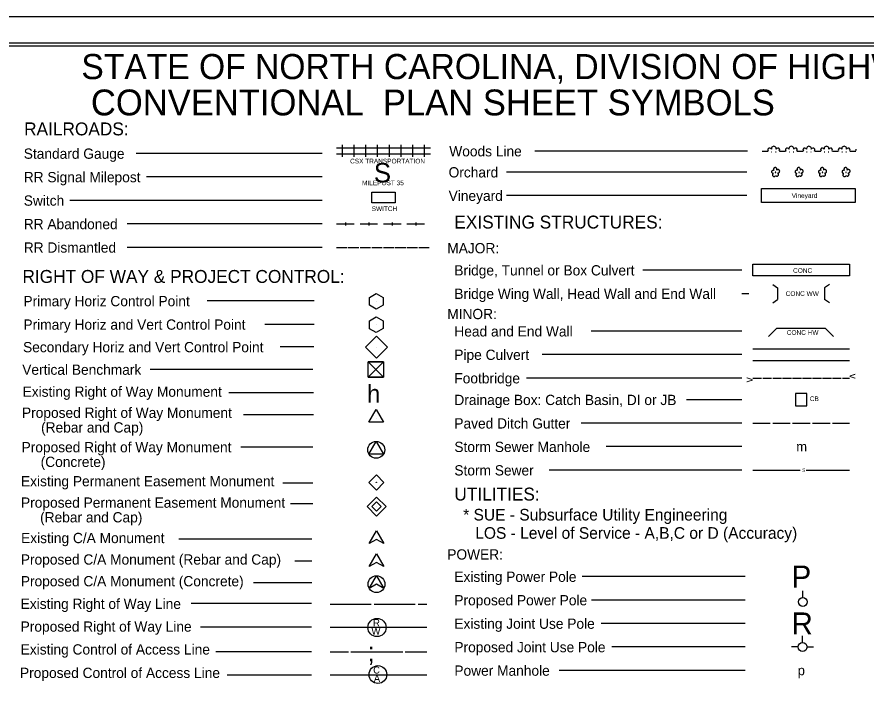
# Model space of a CAD drawing. Extents: x -2196851 to -2112651, y -24168 to 30832.
# Drawn here: x -2168716 to -2132538, y 2370 to 30832 of the extents above; entities that cross this region are included whole.
import ezdxf

# ---------------------------------------------------------------- set-up
doc = ezdxf.new("R2010")
doc.units = 0
for name, color, linetype in [('Default', 7, 'Continuous'), ('Prop ROW Permanent Easement CELL', 7, 'Continuous'), ('Sheet Plot Border Inside CELL', 7, 'Continuous'), ('Sheet Plot Border Outside CELL', 7, 'Continuous'), ('Sheet Symbology CELL', 7, 'Continuous')]:
    doc.layers.add(name, color=color, linetype=linetype)

msp = doc.modelspace()

# ---------------------------------------------------------------- linework, layer by layer
at = {"layer": 'Default'}
for p, q in [((-2153407, 18717), (-2153407, 18717)), ((-2153408, 17719), (-2153408, 17719)), ((-2153401, 16765), (-2153401, 16765)), ((-2153426, 15815), (-2153426, 15815)), ((-2153403, 11004), (-2153403, 11004))]:
    msp.add_line(p, q, dxfattribs=at)
for points in [[(-2153407, 18385), (-2153697, 18549), (-2153697, 18882), (-2153407, 19050), (-2153117, 18885), (-2153117, 18549), (-2153407, 18385)], [(-2153102, 16139), (-2153751, 15490), (-2153426, 15815), (-2153102, 15490), (-2153751, 16139)], [(-2153426, 15815), (-2153102, 16139), (-2153751, 16139), (-2153426, 15815)], [(-2153426, 15815), (-2153751, 15490), (-2153102, 15490), (-2153426, 15815)]]:
    msp.add_lwpolyline(points, dxfattribs=at)
for points in [[(-2153699, 17888), (-2153406, 18051), (-2153113, 17890), (-2153117, 17554), (-2153410, 17384), (-2153699, 17547)], [(-2153871, 16767), (-2153398, 17240), (-2152925, 16766), (-2153398, 16293)], [(-2153751, 16139), (-2153102, 16139), (-2153102, 15490), (-2153751, 15490)], [(-2153727, 11004), (-2153403, 11329), (-2153078, 11004), (-2153403, 10679)]]:
    msp.add_lwpolyline(points, close=True, dxfattribs=at)
msp.add_circle((-2153403, 11004), 6.32, dxfattribs=at)
at = {"layer": 'Prop ROW Permanent Easement CELL'}
msp.add_line((-2153394, 9974), (-2153394, 9974), dxfattribs=at)
for points in [[(-2153394, 10376), (-2152991, 9974), (-2153394, 9571), (-2153796, 9974)], [(-2153394, 10175), (-2153192, 9974), (-2153394, 9772), (-2153595, 9974)]]:
    msp.add_lwpolyline(points, close=True, dxfattribs=at)
at = {"layer": 'Sheet Plot Border Inside CELL'}
msp.add_lwpolyline([(-2196201, -23045), (-2112876, -23045), (-2112876, 29710), (-2196201, 29710)], close=True, dxfattribs=at)
at = {"layer": 'Sheet Plot Border Outside CELL'}
msp.add_lwpolyline([(-2196851, -24168), (-2112651, -24168), (-2112651, 30832), (-2196851, 30832)], close=True, dxfattribs=at)
at = {"layer": 'Sheet Symbology CELL'}
for p, q in [((-2154849, 24880), (-2154849, 25380)), ((-2154349, 24880), (-2154349, 25380)), ((-2153849, 24880), (-2153849, 25380)), ((-2153349, 24880), (-2153349, 25380)), ((-2152849, 24880), (-2152849, 25380)), ((-2152349, 24880), (-2152349, 25380)), ((-2151849, 24880), (-2151849, 25380)), ((-2151349, 24880), (-2151349, 25380)), ((-2155719, 25017), (-2163640, 25017)), ((-2155099, 25255), (-2154599, 25255)), ((-2155099, 25005), (-2154599, 25005)), ((-2154599, 25255), (-2154099, 25255)), ((-2154599, 25005), (-2154099, 25005)), ((-2154099, 25255), (-2153599, 25255)), ((-2154099, 25005), (-2153599, 25005)), ((-2153599, 25255), (-2153099, 25255)), ((-2153599, 25005), (-2153099, 25005)), ((-2153099, 25255), (-2152599, 25255)), ((-2153099, 25005), (-2152599, 25005)), ((-2152599, 25255), (-2152099, 25255)), ((-2152599, 25005), (-2152099, 25005)), ((-2152099, 25255), (-2151599, 25255)), ((-2152099, 25005), (-2151599, 25005)), ((-2151599, 25255), (-2151099, 25255)), ((-2151599, 25005), (-2151099, 25005)), ((-2137587, 25119), (-2146644, 25119)), ((-2136968, 25119), (-2136718, 25119)), ((-2136570, 25094), (-2136545, 25094)), ((-2136395, 25094), (-2136370, 25094)), ((-2136218, 25119), (-2135968, 25119)), ((-2135820, 25094), (-2135795, 25094)), ((-2135645, 25094), (-2135620, 25094)), ((-2135468, 25119), (-2135218, 25119)), ((-2135070, 25094), (-2135045, 25094)), ((-2134895, 25094), (-2134870, 25094)), ((-2134718, 25119), (-2134468, 25119)), ((-2134320, 25094), (-2134295, 25094)), ((-2134145, 25094), (-2134120, 25094)), ((-2133968, 25119), (-2133718, 25119)), ((-2133570, 25094), (-2133545, 25094)), ((-2133395, 25094), (-2133370, 25094)), ((-2133218, 25119), (-2132968, 25119)), ((-2155719, 24017), (-2163197, 24017)), ((-2137616, 24223), (-2147863, 24223)), ((-2137616, 23223), (-2147863, 23223)), ((-2155719, 23017), (-2166465, 23017)), ((-2154724, 22079), (-2154724, 21954)), ((-2153724, 22079), (-2153724, 21954)), ((-2152724, 22079), (-2152724, 21954)), ((-2151724, 22079), (-2151724, 21954)), ((-2155719, 22017), (-2164027, 22017)), ((-2155099, 22017), (-2154349, 22017)), ((-2154099, 22017), (-2153349, 22017)), ((-2153099, 22017), (-2152349, 22017)), ((-2152099, 22017), (-2151349, 22017)), ((-2155719, 21017), (-2164027, 21017)), ((-2155719, 21017), (-2164027, 21017)), ((-2155099, 21017), (-2154649, 21017)), ((-2154599, 21017), (-2154149, 21017)), ((-2154099, 21017), (-2153649, 21017)), ((-2153599, 21017), (-2153149, 21017)), ((-2153099, 21017), (-2152649, 21017)), ((-2152599, 21017), (-2152149, 21017)), ((-2152099, 21017), (-2151649, 21017)), ((-2151599, 21017), (-2151149, 21017)), ((-2137831, 20047), (-2142053, 20047)), ((-2136509, 19441), (-2136304, 19297)), ((-2136304, 19297), (-2136304, 18797)), ((-2134099, 19441), (-2134304, 19297)), ((-2134304, 19297), (-2134304, 18797)), ((-2137831, 19047), (-2137532, 19047)), ((-2156054, 18736), (-2160605, 18736)), ((-2136509, 18654), (-2136304, 18797)), ((-2134099, 18654), (-2134304, 18797)), ((-2156054, 17736), (-2158150, 17736)), ((-2137831, 17448), (-2144246, 17448)), ((-2136689, 17219), (-2136335, 17573)), ((-2136335, 17573), (-2134273, 17573)), ((-2134273, 17573), (-2133919, 17219)), ((-2156069, 16775), (-2157497, 16775)), ((-2137366, 16698), (-2133241, 16698)), ((-2137831, 16448), (-2146341, 16448)), ((-2137366, 16198), (-2133241, 16198)), ((-2156104, 15815), (-2163046, 15815)), ((-2137831, 15448), (-2147005, 15448)), ((-2137366, 15448), (-2136991, 15448)), ((-2136941, 15448), (-2136566, 15448)), ((-2136516, 15448), (-2136141, 15448)), ((-2136091, 15448), (-2135716, 15448)), ((-2135666, 15448), (-2135291, 15448)), ((-2135241, 15448), (-2134866, 15448)), ((-2134816, 15448), (-2134441, 15448)), ((-2134391, 15448), (-2134016, 15448)), ((-2133966, 15448), (-2133591, 15448)), ((-2133541, 15448), (-2133241, 15448)), ((-2156088, 14815), (-2159691, 14815)), ((-2137831, 14526), (-2140191, 14526)), ((-2156083, 13876), (-2159070, 13876)), ((-2153407, 13745), (-2153407, 13745)), ((-2137831, 13526), (-2144679, 13526)), ((-2137366, 13526), (-2136616, 13526)), ((-2136516, 13526), (-2135766, 13526)), ((-2135666, 13526), (-2134916, 13526)), ((-2134816, 13526), (-2134066, 13526)), ((-2133966, 13526), (-2133241, 13526)), ((-2156108, 12506), (-2159183, 12506)), ((-2153407, 12392), (-2153407, 12392)), ((-2137831, 12526), (-2143615, 12526)), ((-2137831, 11526), (-2146041, 11526)), ((-2137366, 11526), (-2135340, 11526)), ((-2135090, 11526), (-2133241, 11526)), ((-2156104, 10971), (-2157394, 10971)), ((-2156104, 10090), (-2157068, 10090)), ((-2153707, 8395), (-2153395, 8935)), ((-2153395, 8935), (-2153082, 8395)), ((-2156154, 8579), (-2161816, 8579)), ((-2153395, 8575), (-2153707, 8395)), ((-2153082, 8395), (-2153395, 8575)), ((-2156149, 7653), (-2156878, 7653)), ((-2153709, 7414), (-2153396, 7954)), ((-2153396, 7954), (-2153084, 7414)), ((-2153396, 7594), (-2153709, 7414)), ((-2153084, 7414), (-2153396, 7594)), ((-2153709, 6489), (-2153396, 7029)), ((-2153396, 7029), (-2153084, 6489)), ((-2137692, 6992), (-2144627, 6992)), ((-2156149, 6727), (-2158633, 6727)), ((-2153396, 6669), (-2153709, 6489)), ((-2153084, 6489), (-2153396, 6669)), ((-2135231, 6097), (-2135231, 6379)), ((-2156171, 5838), (-2161297, 5838)), ((-2155370, 5810), (-2153620, 5810)), ((-2153495, 5810), (-2151745, 5810)), ((-2151620, 5810), (-2151245, 5810)), ((-2137692, 5992), (-2144238, 5992)), ((-2156171, 4838), (-2160897, 4838)), ((-2155370, 4832), (-2151245, 4832)), ((-2137692, 4992), (-2143818, 4992)), ((-2135241, 4180), (-2135241, 4461)), ((-2137692, 3992), (-2143368, 3992)), ((-2135429, 3992), (-2135710, 3992)), ((-2135054, 3992), (-2134773, 3992)), ((-2156171, 3782), (-2160237, 3782)), ((-2155370, 3782), (-2154596, 3782)), ((-2154496, 3782), (-2152276, 3782)), ((-2152176, 3782), (-2151245, 3782)), ((-2137692, 2992), (-2145617, 2992)), ((-2156171, 2791), (-2159753, 2791)), ((-2155370, 2810), (-2151245, 2810))]:
    msp.add_line(p, q, dxfattribs=at)
for points in [[(-2113501, 29582), (-2188501, 29582), (-2188501, -22867), (-2113501, -22867)], [(-2153599, 23365), (-2152599, 23365), (-2152599, 22910), (-2153599, 22910)], [(-2135545, 14260), (-2135064, 14260), (-2135064, 14792), (-2135545, 14792)], [(-2153720, 13565), (-2153407, 14105), (-2153095, 13565)], [(-2153719, 12212), (-2153407, 12752), (-2153094, 12212)]]:
    msp.add_lwpolyline(points, close=True, dxfattribs=at)
for points in [[(-2136344, 24310), (-2136336, 24325), (-2136334, 24340), (-2136336, 24355), (-2136339, 24370), (-2136346, 24383), (-2136354, 24395), (-2136366, 24405), (-2136379, 24413), (-2136396, 24418), (-2136409, 24418), (-2136424, 24415), (-2136439, 24410), (-2136451, 24403), (-2136464, 24393), (-2136471, 24378), (-2136476, 24365), (-2136479, 24350), (-2136479, 24335), (-2136476, 24320), (-2136469, 24308), (-2136459, 24293), (-2136471, 24300), (-2136486, 24303), (-2136501, 24303), (-2136514, 24298), (-2136526, 24293), (-2136539, 24283), (-2136549, 24273), (-2136556, 24260), (-2136559, 24248), (-2136561, 24230), (-2136559, 24218), (-2136554, 24205), (-2136544, 24193), (-2136536, 24183), (-2136524, 24175), (-2136509, 24168), (-2136496, 24165), (-2136481, 24165), (-2136494, 24160), (-2136506, 24150), (-2136514, 24140), (-2136519, 24125), (-2136524, 24110), (-2136524, 24098), (-2136521, 24083), (-2136514, 24070), (-2136506, 24058), (-2136496, 24048), (-2136484, 24040), (-2136471, 24035), (-2136456, 24035), (-2136441, 24035), (-2136429, 24038), (-2136416, 24048), (-2136404, 24055), (-2136391, 24078)], [(-2136391, 24078), (-2136361, 24060), (-2136346, 24055), (-2136331, 24053), (-2136316, 24055), (-2136304, 24060), (-2136291, 24068), (-2136279, 24078), (-2136271, 24090), (-2136266, 24103), (-2136261, 24118), (-2136264, 24133), (-2136266, 24148), (-2136276, 24163), (-2136284, 24173), (-2136296, 24180), (-2136311, 24188), (-2136296, 24185), (-2136279, 24185), (-2136266, 24190), (-2136251, 24198), (-2136239, 24205), (-2136229, 24218), (-2136221, 24233), (-2136219, 24248), (-2136216, 24263), (-2136219, 24278), (-2136224, 24293), (-2136234, 24305), (-2136246, 24318), (-2136259, 24325), (-2136274, 24330), (-2136289, 24333), (-2136304, 24333), (-2136319, 24328), (-2136331, 24320), (-2136344, 24310)], [(-2135344, 24310), (-2135336, 24325), (-2135334, 24340), (-2135336, 24355), (-2135339, 24370), (-2135346, 24383), (-2135354, 24395), (-2135366, 24405), (-2135379, 24413), (-2135396, 24418), (-2135409, 24418), (-2135424, 24415), (-2135439, 24410), (-2135451, 24403), (-2135464, 24393), (-2135471, 24378), (-2135476, 24365), (-2135479, 24350), (-2135479, 24335), (-2135476, 24320), (-2135469, 24308), (-2135459, 24293), (-2135471, 24300), (-2135486, 24303), (-2135501, 24303), (-2135514, 24298), (-2135526, 24293), (-2135539, 24283), (-2135549, 24273), (-2135556, 24260), (-2135559, 24248), (-2135561, 24230), (-2135559, 24218), (-2135554, 24205), (-2135544, 24193), (-2135536, 24183), (-2135524, 24175), (-2135509, 24168), (-2135496, 24165), (-2135481, 24165), (-2135494, 24160), (-2135506, 24150), (-2135514, 24140), (-2135519, 24125), (-2135524, 24110), (-2135524, 24098), (-2135521, 24083), (-2135514, 24070), (-2135506, 24058), (-2135496, 24048), (-2135484, 24040), (-2135471, 24035), (-2135456, 24035), (-2135441, 24035), (-2135429, 24038), (-2135416, 24048), (-2135404, 24055), (-2135391, 24078)], [(-2135391, 24078), (-2135361, 24060), (-2135346, 24055), (-2135331, 24053), (-2135316, 24055), (-2135304, 24060), (-2135291, 24068), (-2135279, 24078), (-2135271, 24090), (-2135266, 24103), (-2135261, 24118), (-2135264, 24133), (-2135266, 24148), (-2135276, 24163), (-2135284, 24173), (-2135296, 24180), (-2135311, 24188), (-2135296, 24185), (-2135279, 24185), (-2135266, 24190), (-2135251, 24198), (-2135239, 24205), (-2135229, 24218), (-2135221, 24233), (-2135219, 24248), (-2135216, 24263), (-2135219, 24278), (-2135224, 24293), (-2135234, 24305), (-2135246, 24318), (-2135259, 24325), (-2135274, 24330), (-2135289, 24333), (-2135304, 24333), (-2135319, 24328), (-2135331, 24320), (-2135344, 24310)], [(-2134344, 24310), (-2134336, 24325), (-2134334, 24340), (-2134336, 24355), (-2134339, 24370), (-2134346, 24383), (-2134354, 24395), (-2134366, 24405), (-2134379, 24413), (-2134396, 24418), (-2134409, 24418), (-2134424, 24415), (-2134439, 24410), (-2134451, 24403), (-2134464, 24393), (-2134471, 24378), (-2134476, 24365), (-2134479, 24350), (-2134479, 24335), (-2134476, 24320), (-2134469, 24308), (-2134459, 24293), (-2134471, 24300), (-2134486, 24303), (-2134501, 24303), (-2134514, 24298), (-2134526, 24293), (-2134539, 24283), (-2134549, 24273), (-2134556, 24260), (-2134559, 24248), (-2134561, 24230), (-2134559, 24218), (-2134554, 24205), (-2134544, 24193), (-2134536, 24183), (-2134524, 24175), (-2134509, 24168), (-2134496, 24165), (-2134481, 24165), (-2134494, 24160), (-2134506, 24150), (-2134514, 24140), (-2134519, 24125), (-2134524, 24110), (-2134524, 24098), (-2134521, 24083), (-2134514, 24070), (-2134506, 24058), (-2134496, 24048), (-2134484, 24040), (-2134471, 24035), (-2134456, 24035), (-2134441, 24035), (-2134429, 24038), (-2134416, 24048), (-2134404, 24055), (-2134391, 24078)], [(-2134391, 24078), (-2134361, 24060), (-2134346, 24055), (-2134331, 24053), (-2134316, 24055), (-2134304, 24060), (-2134291, 24068), (-2134279, 24078), (-2134271, 24090), (-2134266, 24103), (-2134261, 24118), (-2134264, 24133), (-2134266, 24148), (-2134276, 24163), (-2134284, 24173), (-2134296, 24180), (-2134311, 24188), (-2134296, 24185), (-2134279, 24185), (-2134266, 24190), (-2134251, 24198), (-2134239, 24205), (-2134229, 24218), (-2134221, 24233), (-2134219, 24248), (-2134216, 24263), (-2134219, 24278), (-2134224, 24293), (-2134234, 24305), (-2134246, 24318), (-2134259, 24325), (-2134274, 24330), (-2134289, 24333), (-2134304, 24333), (-2134319, 24328), (-2134331, 24320), (-2134344, 24310)], [(-2133344, 24310), (-2133336, 24325), (-2133334, 24340), (-2133336, 24355), (-2133339, 24370), (-2133346, 24383), (-2133354, 24395), (-2133366, 24405), (-2133379, 24413), (-2133396, 24418), (-2133409, 24418), (-2133424, 24415), (-2133439, 24410), (-2133451, 24403), (-2133464, 24393), (-2133471, 24378), (-2133476, 24365), (-2133479, 24350), (-2133479, 24335), (-2133476, 24320), (-2133469, 24308), (-2133459, 24293), (-2133471, 24300), (-2133486, 24303), (-2133501, 24303), (-2133514, 24298), (-2133526, 24293), (-2133539, 24283), (-2133549, 24273), (-2133556, 24260), (-2133559, 24248), (-2133561, 24230), (-2133559, 24218), (-2133554, 24205), (-2133544, 24193), (-2133536, 24183), (-2133524, 24175), (-2133509, 24168), (-2133496, 24165), (-2133481, 24165), (-2133494, 24160), (-2133506, 24150), (-2133514, 24140), (-2133519, 24125), (-2133524, 24110), (-2133524, 24098), (-2133521, 24083), (-2133514, 24070), (-2133506, 24058), (-2133496, 24048), (-2133484, 24040), (-2133471, 24035), (-2133456, 24035), (-2133441, 24035), (-2133429, 24038), (-2133416, 24048), (-2133404, 24055), (-2133391, 24078)], [(-2133391, 24078), (-2133361, 24060), (-2133346, 24055), (-2133331, 24053), (-2133316, 24055), (-2133304, 24060), (-2133291, 24068), (-2133279, 24078), (-2133271, 24090), (-2133266, 24103), (-2133261, 24118), (-2133264, 24133), (-2133266, 24148), (-2133276, 24163), (-2133284, 24173), (-2133296, 24180), (-2133311, 24188), (-2133296, 24185), (-2133279, 24185), (-2133266, 24190), (-2133251, 24198), (-2133239, 24205), (-2133229, 24218), (-2133221, 24233), (-2133219, 24248), (-2133216, 24263), (-2133219, 24278), (-2133224, 24293), (-2133234, 24305), (-2133246, 24318), (-2133259, 24325), (-2133274, 24330), (-2133289, 24333), (-2133304, 24333), (-2133319, 24328), (-2133331, 24320), (-2133344, 24310)], [(-2136386, 24223), (-2136394, 24223), (-2136399, 24220), (-2136404, 24218), (-2136404, 24210), (-2136404, 24205), (-2136399, 24200), (-2136391, 24200), (-2136386, 24200), (-2136381, 24205), (-2136379, 24213), (-2136381, 24218), (-2136386, 24223)], [(-2135386, 24223), (-2135394, 24223), (-2135399, 24220), (-2135404, 24218), (-2135404, 24210), (-2135404, 24205), (-2135399, 24200), (-2135391, 24200), (-2135386, 24200), (-2135381, 24205), (-2135379, 24213), (-2135381, 24218), (-2135386, 24223)], [(-2134386, 24223), (-2134394, 24223), (-2134399, 24220), (-2134404, 24218), (-2134404, 24210), (-2134404, 24205), (-2134399, 24200), (-2134391, 24200), (-2134386, 24200), (-2134381, 24205), (-2134379, 24213), (-2134381, 24218), (-2134386, 24223)], [(-2133386, 24223), (-2133394, 24223), (-2133399, 24220), (-2133404, 24218), (-2133404, 24210), (-2133404, 24205), (-2133399, 24200), (-2133391, 24200), (-2133386, 24200), (-2133381, 24205), (-2133379, 24213), (-2133381, 24218), (-2133386, 24223)], [(-2136996, 23523), (-2132996, 23523), (-2132996, 22923), (-2136996, 22923), (-2136996, 23523)], [(-2137366, 20297), (-2133241, 20297), (-2133241, 19797), (-2137366, 19797), (-2137366, 20297)]]:
    msp.add_lwpolyline(points, dxfattribs=at)
for centre, radius in [((-2153407, 12392), 360), ((-2153396, 6669), 360), ((-2135231, 5910), 188), ((-2153377, 4822), 388), ((-2135241, 3992), 188), ((-2153337, 2816), 379)]:
    msp.add_circle(centre, radius, dxfattribs=at)
for centre, radius, start, end in [((-2136645, 25170), 79.1, 18.435, 219.2315), ((-2136470, 25220), 103, 345.9638, 194.0362), ((-2136295, 25170), 79.1, 320.7685, 161.5651), ((-2135895, 25170), 79.1, 18.435, 219.2315), ((-2135720, 25220), 103, 345.9638, 194.0362), ((-2135545, 25170), 79.1, 320.7685, 161.5651), ((-2135145, 25170), 79.1, 18.435, 219.2315), ((-2134970, 25220), 103, 345.9638, 194.0362), ((-2134795, 25170), 79.1, 320.7685, 161.5651), ((-2134395, 25170), 79.1, 18.435, 219.2315), ((-2134220, 25220), 103, 345.9638, 194.0362), ((-2134045, 25170), 79.1, 320.7685, 161.5651), ((-2133645, 25170), 79.1, 18.435, 219.2315), ((-2133470, 25220), 103, 345.9638, 194.0362), ((-2133295, 25170), 79.1, 320.7685, 161.5651), ((-2132895, 25170), 79.1, 156.251, 203.749)]:
    msp.add_arc(centre, radius, start, end, dxfattribs=at)

# ---------------------------------------------------------------- texts
for s, height, p in [('STATE OF NORTH CAROLINA, DIVISION OF HIGHWAYS', 1070.95, (-2165972, 28184)), ('CONVENTIONAL  PLAN SHEET SYMBOLS', 1101.61, (-2165566, 26640)), ('RAILROADS:', 550, (-2168413, 25789)), ('Woods Line', 437.5, (-2150296, 24893)), ('Standard Gauge', 437.5, (-2168427, 24791)), ('S', 825, (-2153511, 23786)), ('RR Signal Milepost', 437.5, (-2168427, 23791)), ('Orchard', 437.5, (-2150324, 23996)), ('Switch', 437.5, (-2168427, 22791)), ('Vineyard', 437.5, (-2150324, 22996)), ('RR Abandoned', 437.5, (-2168427, 21791)), ('EXISTING STRUCTURES:', 550, (-2150080, 21820)), ('RR Dismantled', 437.5, (-2168427, 20791)), ('MAJOR:', 437.5, (-2150381, 20764)), ('Bridge, Tunnel or Box Culvert', 437.5, (-2150080, 19820)), ('RIGHT OF WAY & PROJECT CONTROL:', 550, (-2168484, 19503)), ('CONC', 200, (-2135645, 19929)), ('Bridge Wing Wall, Head Wall and End Wall', 437.5, (-2150080, 18820)), ('Primary Horiz Control Point', 437.5, (-2168441, 18508)), ('MINOR:', 437.5, (-2150381, 17958)), ('Primary Horiz and Vert Control Point', 437.5, (-2168441, 17508)), ('Head and End Wall', 437.5, (-2150080, 17220)), ('Secondary Horiz and Vert Control Point', 437.5, (-2168457, 16548)), ('Pipe Culvert', 437.5, (-2150080, 16221)), ('Vertical Benchmark', 437.5, (-2168491, 15587)), ('Footbridge', 437.5, (-2150079, 15221)), ('h', 750, (-2153796, 14406)), ('Existing Right of Way Monument', 437.5, (-2168476, 14651)), ('Drainage Box: Catch Basin, DI or JB', 437.5, (-2150079, 14299)), ('Proposed Right of Way Monument', 437.5, (-2168502, 13753)), ('Paved Ditch Gutter', 437.5, (-2150079, 13298)), ('     (Rebar and Cap)', 437.5, (-2168502, 13128)), ('Proposed Right of Way Monument', 437.5, (-2168520, 12285)), ('Storm Sewer Manhole', 437.5, (-2150079, 12298)), ('m', 412, (-2135510, 12320)), ('     (Concrete)', 437.5, (-2168520, 11660)), ('Storm Sewer', 437.5, (-2150079, 11298)), ('S', 150, (-2135260, 11451)), ('Existing Permanent Easement Monument', 437.5, (-2168545, 10836)), ('UTILITIES:', 550, (-2150080, 10230)), ('Proposed Permanent Easement Monument', 437.5, (-2168543, 9924)), ('     (Rebar and Cap)', 437.5, (-2168543, 9299)), ('Existing C/A Monument', 437.5, (-2168542, 8415)), ('Proposed C/A Monument (Rebar and Cap)', 437.5, (-2168552, 7500)), ('POWER:', 437.5, (-2150381, 7715)), ('P', 938, (-2135710, 6523)), ('Proposed C/A Monument (Concrete)', 437.5, (-2168552, 6575)), ('Existing Power Pole', 437.5, (-2150079, 6765)), ('Proposed Power Pole', 437.5, (-2150079, 5765)), ('Existing Right of Way Line', 437.5, (-2168559, 5611)), ('R', 938, (-2135710, 4523)), ('Proposed Right of Way Line', 437.5, (-2168559, 4642)), ('R', 304, (-2153544, 4868)), ('Existing Joint Use Pole', 437.5, (-2150079, 4766)), ('W', 304, (-2153613, 4510)), ('Existing Control of Access Line', 437.5, (-2168559, 3669)), (';', 825, (-2153780, 3373)), ('Proposed Joint Use Pole', 437.5, (-2150078, 3765)), ('Proposed Control of Access Line', 437.5, (-2168586, 2670)), ('C', 297, (-2153539, 2860)), ('Power Manhole', 437.5, (-2150078, 2765)), ('p', 412, (-2135448, 2786)), ('A', 297, (-2153509, 2503))]:
    msp.add_text(s, height=height, dxfattribs=at).set_placement(p)
for s, height, rotation, p in [('CSX TRANSPORTATION', 200, 360, (-2154521, 24593)), ('MILEPOST 35', 200, 360, (-2154012, 23664)), ('Vineyard', 200, 0, (-2135705, 23123)), ('SWITCH', 200, 360, (-2153602, 22564)), ('CONC WW', 200, 0, (-2135960, 18947)), ('CONC HW', 200, 360, (-2135914, 17290)), ('v', 330, 270.2409, (-2133242, 15635)), ('v', 330, 89.7591, (-2137367, 15261)), ('CB', 200, 360, (-2134932, 14467)), ('* SUE - Subsurface Utility Engineering', 495, 360, (-2149703, 9379)), ('LOS - Level of Service - A,B,C or D (Accuracy) ', 495, 360, (-2149189, 8601))]:
    msp.add_text(s, height=height, rotation=rotation, dxfattribs=at).set_placement(p)

doc.saveas('drawing.dxf')
